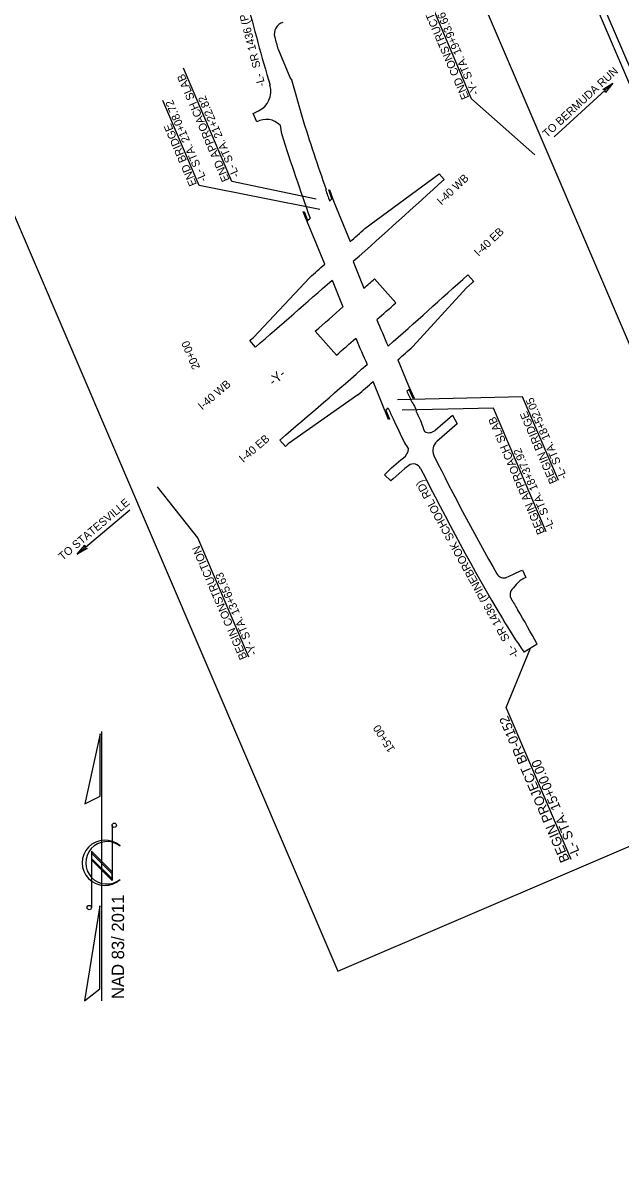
# Model space of a CAD drawing. Extents: x 1550250 to 1553210, y 808906 to 812497.
# Drawn here: x 1551407 to 1552154, y 809656 to 811095 of the extents above; entities that cross this region are included whole.
import ezdxf

# ---------------------------------------------------------------- set-up
doc = ezdxf.new("R2010")
doc.units = 0
for name, color, linetype in [('P_RDY_DSN_Text', 7, 'Continuous'), ('P_RDY_Shade_Light', 7, 'Continuous'), ('Prop DSN Text', 7, 'Continuous'), ('Prop Terminator Cell', 7, 'Continuous'), ('Sheet Title CELL', 7, 'Continuous'), ('Sheet_North_Arrow_CELL', 7, 'Continuous'), ('Sheet_Plan_CELL', 7, 'Continuous'), ('Sheet_Title_CELL', 7, 'Continuous')]:
    doc.layers.add(name, color=color, linetype=linetype)

msp = doc.modelspace()

# ---------------------------------------------------------------- linework, layer by layer
at = {"layer": 'P_RDY_DSN_Text'}
for points in [[(1552046.5, 810930.6), (1551967.3, 811000.3), (1551909.6, 811136.6)], [(1551773.1, 810875.2), (1551668, 810897.1), (1551607.5, 811038.6)], [(1551777.9, 810862), (1551627.2, 810892.1), (1551581.9, 810998.1)], [(1552075.7, 810523.7), (1552030.9, 810628.3), (1551874.9, 810624.4)], [(1552060.7, 810459.7), (1551994.7, 810614), (1551880.8, 810611.6)], [(1551689.2, 810303.2), (1551625.5, 810452.1), (1551575, 810515.9)], [(1552091.7, 810050.5), (1552010.4, 810240.3), (1552041.1, 810314.3)]]:
    msp.add_lwpolyline(points, dxfattribs=at)
at = {"layer": 'P_RDY_Shade_Light'}
for p, q in [((1551785.5, 810887.4), (1551784.9, 810886.9)), ((1551846.2, 810775.5), (1551872.7, 810745.6)), ((1551798.5, 810680.2), (1551772.2, 810710.3)), ((1551892.8, 810621.5), (1551893.3, 810622)), ((1551898.4, 810611.1), (1551897.8, 810610.8)), ((1552049.2, 810319.3), (1552032.9, 810309.2))]:
    msp.add_line(p, q, dxfattribs=at)
for points in [[(1551725.6, 811062.3), (1551741.4, 811025.4), (1551742, 811025.6), (1551755.6, 810977.5)], [(1551699.2, 810971.6), (1551694.7, 810982.2), (1551701.1, 810985.2)], [(1551834.1, 810838.5), (1551926.9, 810906.7), (1551933.2, 810899.7)], [(1551790, 810872.6), (1551793, 810875.3), (1551789, 810886.6), (1551789.9, 810886.9), (1551795.3, 810871.7), (1551815.6, 810822)], [(1551783.9, 810793.8), (1551757.2, 810859.3), (1551758.1, 810859.6), (1551762.6, 810848.5), (1551765.8, 810851.3)], [(1551697.3, 810690.4), (1551690.4, 810698.5), (1551691.2, 810699.2), (1551694.9, 810702.4), (1551765.3, 810777.4)], [(1551962.6, 810780.5), (1551970, 810772.3), (1551968, 810770.4), (1551961.2, 810764.2), (1551894.1, 810691.1)], [(1551875.2, 810674.4), (1551888.4, 810642.1), (1551895.5, 810626.7), (1551894.6, 810626.3), (1551889.5, 810637.3), (1551886.6, 810634.8)], [(1551863.1, 810614.1), (1551860.1, 810611.4), (1551864.7, 810600.3), (1551863.7, 810599.9), (1551844.4, 810647.3)], [(1551825.4, 810630.7), (1551738.4, 810569.4), (1551734.8, 810566.3), (1551727.9, 810574.3)], [(1551921.8, 810586.4), (1551943.7, 810605.5), (1551949.2, 810594.3), (1551924.1, 810572.5)], [(1551888.9, 810542.6), (1551883.8, 810538.9), (1551869.3, 810526), (1551866.7, 810523.3), (1551858.8, 810530.6), (1551867.3, 810539.6), (1551879, 810549.5), (1551882.3, 810552)], [(1552011.4, 810402.9), (1552013.5, 810403.7), (1552020.4, 810407.1), (1552028.3, 810410.7), (1552031, 810411.9), (1552035, 810402.7), (1552032.4, 810401.3), (1552031.8, 810401), (1552031.3, 810400.7), (1552030.7, 810400.3), (1552030.2, 810400), (1552029.5, 810399.5), (1552028.9, 810399.1), (1552027.7, 810398.3), (1552026.4, 810397.2), (1552025.4, 810396.2), (1552024.7, 810395.6), (1552024.3, 810395.1), (1552023.8, 810394.7), (1552023.3, 810394.1), (1552023, 810393.8), (1552019.5, 810389.7), (1552017.8, 810387.6)]]:
    msp.add_lwpolyline(points, dxfattribs=at)
for centre, radius, start, end in [((1554524.2, 811845.1), 2928, 194.2411, 196.4227), ((1551735.9, 811081.4), 15, 106, 195.3183), ((1554524.2, 811845.1), 2906, 195.3183, 195.6275), ((1551689.7, 811009.7), 27, 294.9692, 16.4227), ((1551710.9, 810950.7), 24, 44.141, 119.2133), ((1554524.2, 811845.1), 2901.3, 197.4005, 199.2759), ((1554591.1, 811489.5), 2910.2, 190.3357, 190.5682), ((1554524.2, 811845.1), 2932, 197.6574, 199.8143), ((1544245.7, 819324.7), 11405.2, 311.61158, 312.37947), ((1554524.2, 811845.1), 2902, 199.2813, 199.5795), ((1544245.7, 819324.7), 11384.2, 311.6783, 311.80331), ((1544245.7, 819324.7), 11384.2, 311.34006, 311.46505), ((1554524.2, 811845.1), 2900.4, 201.1755, 201.8905), ((1544245.7, 819324.7), 11405.2, 310.79503, 311.43356), ((1554524.2, 811845.1), 2933.6, 201.4162, 202.1212), ((1544245.7, 819324.7), 11439.2, 311.54934, 311.63796), ((1544245.7, 819324.7), 11513.2, 311.4234, 312.08736), ((1544245.7, 819324.7), 11439.2, 311.14409, 311.37272), ((1544245.7, 819324.7), 11479.2, 311.47967, 311.63796), ((1554524.2, 811845.1), 2900.4, 202.7273, 203.435), ((1544245.7, 819324.7), 11479.2, 311.14431, 311.30461), ((1554524.2, 811845.1), 2933.6, 202.9465, 203.6447), ((1544243.9, 819329.1), 11538.7, 311.40434, 311.52928), ((1544245.7, 819324.7), 11513.2, 310.53288, 311.24961), ((1544243.9, 819329.1), 11538.7, 311.07551, 311.20049), ((1554524.2, 811845.1), 2902, 204.6502, 204.9387), ((1554524.2, 811845.1), 2932, 204.8269, 205.1121), ((1554524.2, 811845.1), 2901.3, 204.9348, 205.1722), ((1554524.2, 811845.1), 2932, 205.1121, 205.7625), ((1554524.2, 811845.1), 2902, 205.1721, 205.4792), ((1554653.7, 811503.3), 2894.9, 198.2497, 198.4992), ((1551913.9, 810595.4), 12, 242.6337, 311.0211), ((1554332.7, 812152.3), 2915.4, 212.8525, 213.0366), ((1551933.9, 810561.2), 15, 131.0211, 204.3749), ((1551872.2, 810565.3), 16.7, 307.4014, 351.9162), ((1554524.2, 811845.1), 2906, 206.3571, 209.6587), ((1551894.7, 810534.4), 10, 26.4952, 125.582), ((1554524.2, 811845.1), 2928, 206.4952, 210.6719), ((1552007.6, 810412.1), 10, 209.6587, 292.2996), ((1552025.4, 810381.2), 10, 140.1663, 210.365), ((1554524.2, 811845.1), 2906, 210.365, 210.6719), ((1551064.6, 809793.3), 1116.3, 28.1132, 30.6719), ((1552636.7, 810725.7), 733.5, 210.6719, 214.5933)]:
    msp.add_arc(centre, radius, start, end, dxfattribs=at)
at = {"layer": 'Prop DSN Text'}
for p, q in [((1552070.5, 810952.8), (1552143.6, 811020.1)), ((1551474.8, 810431.6), (1551540.6, 810486.9))]:
    msp.add_line(p, q, dxfattribs=at)
at = {"layer": 'Prop Terminator Cell'}
for points in [[(1552131.4, 811012.2), (1552143.6, 811020.1), (1552134.7, 811008.4), (1552134.3, 811011.6)], [(1551487.4, 810439), (1551474.8, 810431.6), (1551484.2, 810442.9), (1551484.5, 810439.7)]]:
    msp.add_lwpolyline(points, close=True, dxfattribs=at)
at = {"layer": 'Sheet_North_Arrow_CELL'}
for p, q in [((1551505.7, 809873.9), (1551505.7, 810210.3)), ((1551518.4, 810093.2), (1551518.4, 810024.2)), ((1551527.9, 810067.5), (1551528.3, 810067.2)), ((1551518.4, 810035), (1551492.7, 810060.7)), ((1551492.7, 810060.7), (1551492.7, 809990.5)), ((1551518.4, 810032.4), (1551492.7, 810058.1)), ((1551492.7, 810058.1), (1551492.7, 810051.8)), ((1551518.4, 810026.1), (1551492.7, 810051.8)), ((1551492.7, 810051.8), (1551518.4, 810026.1)), ((1551518.4, 810024.2), (1551492.7, 810049.9)), ((1551518.4, 810026.1), (1551518.4, 810032.4))]:
    msp.add_line(p, q, dxfattribs=at)
for points in [[(1551503.4, 810207.3), (1551484.2, 810120), (1551503.4, 810129.7)], [(1551503, 809992.4), (1551483.9, 809873.9), (1551503, 809888.9)]]:
    msp.add_lwpolyline(points, close=True, dxfattribs=at)
for centre in [(1551521.1, 810093.2), (1551489.9, 809990.4)]:
    msp.add_circle(centre, 2.74, dxfattribs=at)
for centre, radius, start, end in [((1551509.3, 810046.3), 28.3, 47.84, 312.3941), ((1551512, 810046.3), 26.5, 53.095, 308.6287)]:
    msp.add_arc(centre, radius, start, end, dxfattribs=at)
at = {"layer": 'Sheet_Plan_CELL'}
msp.add_lwpolyline([(1551190.2, 811336.1), (1551800.2, 809911.1), (1552391.4, 810164.1), (1551781.4, 811589.2)], close=True, dxfattribs=at)
at = {"layer": 'Sheet_Title_CELL'}
for p, q in [((1552747.8, 809656.4), (1551686.1, 812136.6)), ((1552253.4, 810833.3), (1552059.9, 811285.3))]:
    msp.add_line(p, q, dxfattribs=at)

# ---------------------------------------------------------------- texts
at = {"layer": 'P_RDY_DSN_Text'}
for s, height, rotation, p in [('-L-  SR 1436 (PINEBROOK SCHOOL RD)', 10, 104.2411, (1551709.9, 811017.1)), ('END CONSTRUCTION', 10, 113.1736, (1551964.6, 811002.2)), ('-Y- STA. 19+93.66', 10, 113.1736, (1551977, 811007.5)), ('END APPROACH SLAB', 10, 113.1736, (1551665.3, 810899.3)), ('-L- STA. 21+08.72', 10, 113.1736, (1551636.9, 810899.1)), ('-L- STA. 21+22.82', 10, 113.1736, (1551677.7, 810904.6)), ('END BRIDGE', 10, 113.1736, (1551624.5, 810893.8)), ('I-40 WB', 10, 43.4476, (1551929.7, 810867)), ('I-40 EB', 10, 43.2289, (1551976.1, 810802.9)), ('20+00', 10, 113.1736, (1551628.5, 810664.8)), ('-Y-', 12, 40.8561, (1551720, 810641.3)), ('I-40 WB', 10, 40.7759, (1551631, 810611.1)), ('-L- STA. 18+52.05', 10, 113.1736, (1552086.9, 810527.5)), ('BEGIN APPROACH SLAB', 10, 113.1736, (1552059.1, 810458.9)), ('BEGIN BRIDGE', 10, 113.1736, (1552074.5, 810522.2)), ('I-40 EB', 10, 40.5572, (1551682.2, 810545.4)), ('-L- STA. 18+37.92', 10, 113.1736, (1552071.5, 810464.3)), ('-L-  SR 1436 (PINEBROOK SCHOOL RD)', 10, 118.8173, (1552026.8, 810305.2)), ('BEGIN CONSTRUCTION', 10, 113.1736, (1551687.4, 810302.5)), ('-Y- STA. 13+65.63', 10, 113.1736, (1551699.8, 810307.8)), ('BEGIN PROJECT BR-0152', 12, 113.1736, (1552090, 810049.7)), ('15+00', 10, 122.621, (1551872.2, 810188.2)), ('-L- STA. 15+00.00', 12, 113.1736, (1552104.3, 810055.8))]:
    msp.add_text(s, height=height, rotation=rotation, dxfattribs=at).set_placement(p)
at = {"layer": 'Prop DSN Text'}
for s, rotation, p in [('TO BERMUDA RUN', 42.6287, (1552061.6, 810951.3)), ('TO STATESVILLE', 40.1021, (1551456.6, 810423.3))]:
    msp.add_text(s, height=10, rotation=rotation, dxfattribs=at).set_placement(p)
at = {"layer": 'Sheet Title CELL'}
msp.add_text('DIVISION OF HIGHWAYS', height=12.938, rotation=113.1759, dxfattribs=at).set_placement((1552194.9, 811064.9))
at = {"layer": 'Sheet_North_Arrow_CELL'}
msp.add_text('NAD 83/ 2011', height=15.525, rotation=90, dxfattribs=at).set_placement((1551533.4, 809876.1))

doc.saveas('drawing.dxf')
